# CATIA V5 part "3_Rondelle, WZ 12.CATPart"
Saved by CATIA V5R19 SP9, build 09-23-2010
Part number: 3_Rondelle, WZ 12
Revision: ANY
Definition: UNKNOWN
Nomenclature: 3_Rondelle, WZ 12
Source: Unknown
Bounding box of the stored display mesh (mm): x -10 to 10, y 0 to 2, z -10 to 10
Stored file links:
  Y:\fin de projet cabestan poupee\3_Rondelle, WZ 12.CATPart
  Ass_arbre poupee_1.CATProduct
  Y:\bricolage cabestan\6_axe.CATPart
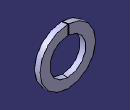
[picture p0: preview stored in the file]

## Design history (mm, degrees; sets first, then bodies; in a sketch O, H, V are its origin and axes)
Body1 "NONE" (main body)
  Solid1: solid without history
